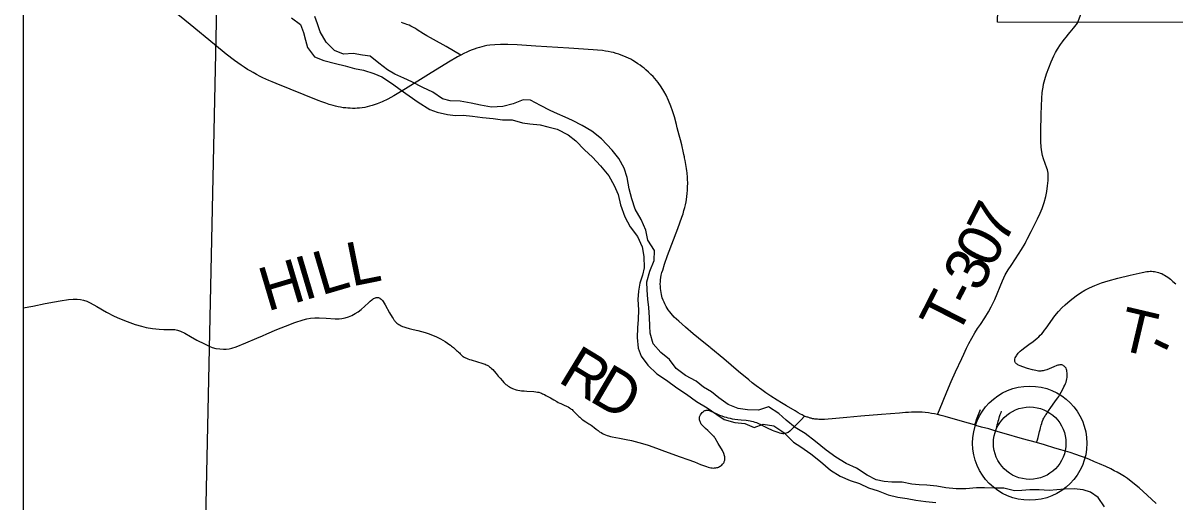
# Model space of a CAD drawing. Extents: x 0 to 34, y 0 to 22.
# Drawn here: x 2.1 to 3.6, y 17.772 to 18.396 of the extents above; entities that cross this region are included whole.
import ezdxf

# ---------------------------------------------------------------- set-up
doc = ezdxf.new("R2010")
doc.units = 0
for name, color, linetype in [('GM_X_Corporation', 7, 'Continuous'), ('GM_X_Major_River', 7, 'Continuous'), ('GM_X_State_Route', 7, 'Continuous'), ('GM_X_Township_Road', 7, 'Continuous'), ('GM_X_Township_Road_Text', 7, 'Continuous'), ('GM_X_Township_Text', 7, 'Continuous'), ('GM_X_Unincorporated', 7, 'Continuous'), ('GM_X_Unincorporated_Location', 7, 'Continuous'), ('SH_Data', 7, 'Continuous')]:
    doc.layers.add(name, color=color, linetype=linetype)

msp = doc.modelspace()

# ---------------------------------------------------------------- linework, layer by layer
at = {"layer": 'GM_X_Corporation'}
msp.add_lwpolyline([(4.6584, 17.4085), (4.4004, 17.4134), (4.4034, 17.9703), (4.4042, 18.3894), (4.0024, 18.3976), (3.4726, 18.3965), (3.3689, 18.3973), (3.3767, 18.6788), (3.3859, 18.705), (3.3893, 18.721), (3.3872, 18.7823), (3.3779, 18.9241), (3.3711, 18.9531), (3.3709, 19.4088), (3.3147, 19.4093), (2.7824, 19.4152), (2.1, 19.4241), (2.1, 14.1)], dxfattribs=at)
msp.add_lwpolyline([(2.1, 18.4215), (2.1, 17.4478), (2.3314, 17.4451), (2.3525, 18.417)], close=True, dxfattribs=at)
at = {"layer": 'GM_X_Major_River'}
for points in [[(3.4461, 17.7878), (3.4359, 17.7869), (3.423, 17.7875), (3.4109, 17.7877), (3.4006, 17.7868), (3.3908, 17.7863), (3.3771, 17.7899), (3.3669, 17.7898), (3.3521, 17.7904), (3.3414, 17.7902), (3.3274, 17.7889), (3.3149, 17.7891), (3.3016, 17.7901), (3.2899, 17.7922), (3.277, 17.7935), (3.2667, 17.7941), (3.2572, 17.7948), (3.2447, 17.7976), (3.2314, 17.7978), (3.2212, 17.7984), (3.2109, 17.8006), (3.199, 17.8069), (3.1853, 17.8158), (3.1719, 17.8217), (3.1585, 17.8302), (3.1459, 17.8395), (3.1317, 17.8507), (3.1183, 17.8611), (3.1053, 17.8689), (3.0938, 17.8786), (3.0842, 17.8872), (3.0708, 17.8958), (3.0576, 17.8914), (3.0432, 17.892), (3.0311, 17.8937), (3.0181, 17.8989), (3.0062, 17.9074), (2.9966, 17.9152), (2.9859, 17.9212), (2.9764, 17.9294), (2.9626, 17.9368), (2.9503, 17.9457), (2.9418, 17.9574), (2.9303, 17.9667), (2.9203, 17.9779), (2.9167, 17.9919), (2.9162, 18.0014), (2.9157, 18.012), (2.9148, 18.0253), (2.9135, 18.0362), (2.9126, 18.048), (2.9124, 18.0586), (2.916, 18.0727), (2.9219, 18.0864), (2.9221, 18.0997), (2.9136, 18.1129), (2.9111, 18.1261), (2.9049, 18.14), (2.8971, 18.1532), (2.8927, 18.1668), (2.8892, 18.1797), (2.8867, 18.1948), (2.8827, 18.2069), (2.8757, 18.2193), (2.8669, 18.2305), (2.8534, 18.2452), (2.8407, 18.2552), (2.8281, 18.2626), (2.8155, 18.2689), (2.806, 18.2733), (2.7957, 18.2778), (2.7862, 18.2822), (2.7739, 18.2885), (2.7606, 18.2955), (2.7511, 18.2961), (2.7383, 18.2906), (2.7247, 18.287), (2.7099, 18.2865), (2.6958, 18.2889), (2.6833, 18.2914), (2.6692, 18.2942), (2.6563, 18.2948), (2.6461, 18.297), (2.6334, 18.3059), (2.6205, 18.3118), (2.6063, 18.3192), (2.596, 18.324), (2.5842, 18.3295), (2.5746, 18.3351), (2.5632, 18.3436), (2.552, 18.3526), (2.5418, 18.3543), (2.53, 18.3561), (2.5171, 18.3555), (2.5057, 18.3603), (2.4945, 18.3711), (2.4871, 18.3847), (2.4836, 18.3949), (2.48, 18.4047)], [(2.4494, 18.4028), (2.4612, 18.3942), (2.4652, 18.3836), (2.4676, 18.3738), (2.4704, 18.364), (2.4796, 18.352), (2.4918, 18.3472), (2.5067, 18.3432), (2.5196, 18.3404), (2.5314, 18.3368), (2.5432, 18.3346), (2.5569, 18.3303), (2.5672, 18.3259), (2.581, 18.3166), (2.5909, 18.3095), (2.6028, 18.3013), (2.6146, 18.2927), (2.6296, 18.2835), (2.6391, 18.2798), (2.6528, 18.2766), (2.663, 18.2756), (2.6729, 18.2757), (2.6854, 18.2747), (2.6983, 18.273), (2.712, 18.2717), (2.7241, 18.27), (2.737, 18.2698), (2.7504, 18.2661), (2.7599, 18.2648), (2.7735, 18.2634), (2.7834, 18.2609), (2.7956, 18.2577), (2.8097, 18.2503), (2.8197, 18.2424), (2.8312, 18.2308), (2.8416, 18.2211), (2.852, 18.2099), (2.8628, 18.1967), (2.8698, 18.1843), (2.8749, 18.1723), (2.8781, 18.159), (2.8836, 18.1432), (2.8906, 18.1304), (2.9002, 18.1176), (2.9061, 18.1044), (2.9082, 18.0915), (2.9088, 18.0771), (2.9066, 18.0672), (2.9033, 18.057), (2.9016, 18.0467), (2.9006, 18.0357), (2.9012, 18.0224), (2.901, 18.0095), (2.9, 17.9989), (2.8998, 17.986), (2.9011, 17.9724), (2.905, 17.9618), (2.9135, 17.9502), (2.9254, 17.9389), (2.938, 17.9304), (2.9514, 17.9207), (2.9641, 17.9122), (2.9771, 17.9028), (2.9909, 17.8943), (3.0035, 17.8858), (3.013, 17.8794), (3.0267, 17.8755), (3.04, 17.8741), (3.0522, 17.869), (3.0639, 17.8733), (3.0776, 17.8712), (3.0906, 17.8623), (3.1033, 17.8496), (3.1129, 17.8436), (3.1259, 17.8343), (3.1385, 17.8246), (3.1516, 17.8131), (3.1638, 17.8056), (3.1768, 17.7997), (3.1893, 17.7957), (3.2008, 17.7902), (3.2134, 17.7862), (3.2263, 17.7811), (3.2389, 17.7782), (3.251, 17.7761), (3.2624, 17.774), (3.2757, 17.7726), (3.2886, 17.7713)], [(3.5082, 17.7655), (3.4997, 17.7776), (3.4898, 17.7846), (3.4802, 17.7875), (3.4685, 17.7889), (3.456, 17.7884), (3.4461, 17.7878)]]:
    msp.add_lwpolyline(points, dxfattribs=at)
at = {"layer": 'GM_X_State_Route'}
for points in [[(2.9949, 17.973), (2.9865, 17.9798), (2.9724, 17.991), (2.9624, 17.9994), (2.9537, 18.0073), (2.948, 18.0128), (2.9439, 18.0173), (2.9421, 18.0196), (2.9402, 18.0221), (2.9388, 18.0242), (2.9375, 18.0264), (2.9365, 18.0281), (2.9357, 18.0299), (2.9346, 18.0324), (2.9334, 18.035), (2.9324, 18.0377), (2.9318, 18.0401), (2.9312, 18.0423), (2.9308, 18.0447), (2.9305, 18.0474), (2.9302, 18.0499), (2.93, 18.0526), (2.9298, 18.0561), (2.9299, 18.0586), (2.9301, 18.0615), (2.9306, 18.0644), (2.9311, 18.0674), (2.9319, 18.0707), (2.9329, 18.074), (2.9352, 18.0817), (2.9391, 18.0928), (2.9527, 18.1282), (2.9554, 18.1355), (2.9579, 18.1429), (2.9594, 18.1475), (2.9606, 18.1518), (2.9616, 18.1557), (2.9625, 18.1591), (2.9633, 18.163), (2.9638, 18.1662), (2.9644, 18.17), (2.9649, 18.1738), (2.9652, 18.1781), (2.9654, 18.182), (2.9656, 18.1876), (2.9654, 18.192), (2.9653, 18.1945), (2.9648, 18.2007), (2.9645, 18.2032), (2.964, 18.2063), (2.9621, 18.2167), (2.9614, 18.2203), (2.9612, 18.2215), (2.9606, 18.2246), (2.96, 18.227), (2.9576, 18.2373), (2.9559, 18.2439), (2.9544, 18.2499), (2.9519, 18.2595), (2.9509, 18.2637), (2.9481, 18.2739), (2.9458, 18.2817), (2.9437, 18.2875), (2.9406, 18.2951), (2.9375, 18.3019), (2.9345, 18.3074), (2.9311, 18.3127), (2.927, 18.3183), (2.9249, 18.3209), (2.9226, 18.3235), (2.9203, 18.3261), (2.9174, 18.3289), (2.9142, 18.332), (2.9109, 18.3349), (2.9086, 18.337), (2.9061, 18.3389), (2.9036, 18.3409), (2.9005, 18.3429), (2.8976, 18.345), (2.8942, 18.347), (2.8912, 18.3488), (2.8882, 18.3503), (2.8852, 18.3517), (2.8825, 18.3529), (2.879, 18.3543), (2.8758, 18.3555), (2.8723, 18.3565), (2.8687, 18.3575), (2.8656, 18.3582), (2.862, 18.3589), (2.8586, 18.3595), (2.8546, 18.36), (2.8478, 18.3608), (2.8422, 18.3612), (2.8107, 18.3633), (2.7678, 18.366), (2.7436, 18.3674), (2.7311, 18.3679), (2.7218, 18.368), (2.7143, 18.3676), (2.7079, 18.3671), (2.7039, 18.3665), (2.7005, 18.3658), (2.6973, 18.3651), (2.6944, 18.3643), (2.691, 18.3633), (2.6876, 18.3621), (2.6847, 18.361), (2.6815, 18.3598), (2.6778, 18.3581), (2.6741, 18.3562), (2.6701, 18.3541), (2.6658, 18.3519), (2.654, 18.345), (2.628, 18.3291), (2.5979, 18.3104), (2.5826, 18.3009), (2.5751, 18.2967), (2.5678, 18.2933), (2.5609, 18.2906), (2.5545, 18.2885), (2.5513, 18.2875), (2.5481, 18.2866), (2.545, 18.2859), (2.5416, 18.2854), (2.5383, 18.2851), (2.5352, 18.2849), (2.5323, 18.2848), (2.5292, 18.2848), (2.5259, 18.2849), (2.5231, 18.285), (2.5202, 18.2853), (2.5168, 18.2856), (2.5133, 18.2862), (2.5103, 18.2868), (2.5069, 18.2876), (2.5037, 18.2884), (2.4984, 18.29), (2.4941, 18.2915), (2.4891, 18.2932), (2.4842, 18.2951), (2.4297, 18.3171), (2.4242, 18.3194), (2.4199, 18.3212), (2.4161, 18.3229), (2.4124, 18.3247), (2.4087, 18.3265), (2.4038, 18.3291), (2.3995, 18.3314), (2.3959, 18.3335), (2.3923, 18.3356), (2.3879, 18.3383), (2.384, 18.3409), (2.3754, 18.347), (2.3646, 18.3553), (2.3491, 18.3678), (2.3175, 18.3939), (2.2945, 18.4128)], [(3.5756, 17.7696), (3.5637, 17.7805), (3.5531, 17.79), (3.545, 17.7969), (3.5381, 17.8022), (3.5341, 17.8051), (3.5299, 17.8077), (3.5248, 17.8105), (3.5209, 17.8125), (3.5162, 17.8148), (3.5097, 17.8179), (3.5017, 17.8215), (3.4951, 17.8243), (3.4878, 17.8274), (3.482, 17.8296), (3.477, 17.8315), (3.4707, 17.8338), (3.4633, 17.8363), (3.4514, 17.8399), (3.4437, 17.8421), (3.4301, 17.8461), (3.4196, 17.8491), (3.4016, 17.8542), (3.3774, 17.8611), (3.3668, 17.8641), (3.3639, 17.8649), (3.3574, 17.8669), (3.3482, 17.8694), (3.3405, 17.8716), (3.3389, 17.8721), (3.3232, 17.8765), (3.3005, 17.8832), (3.2956, 17.8845), (3.2909, 17.8856), (3.2867, 17.8865), (3.2829, 17.8872), (3.2791, 17.8878), (3.2748, 17.8884), (3.2709, 17.8887), (3.2681, 17.8889), (3.2659, 17.889), (3.2613, 17.889), (3.2568, 17.8888), (3.2528, 17.8886), (3.2489, 17.8882), (3.2412, 17.8876), (3.2177, 17.8856), (3.1911, 17.8835), (3.1725, 17.8818), (3.1583, 17.8804), (3.1437, 17.8792), (3.1407, 17.8792), (3.1385, 17.8792), (3.1364, 17.8793), (3.1344, 17.8795), (3.1329, 17.8796), (3.1312, 17.8798), (3.1296, 17.88), (3.1289, 17.8801), (3.1281, 17.8803), (3.1272, 17.8805), (3.1262, 17.8808), (3.1251, 17.8811), (3.1241, 17.8814), (3.123, 17.8817), (3.1218, 17.8821), (3.1209, 17.8825), (3.1197, 17.8829), (3.1186, 17.8833), (3.1176, 17.8838), (3.1159, 17.8845), (3.1144, 17.8852), (3.1122, 17.8863), (3.1093, 17.8879), (3.1053, 17.8904), (3.094, 17.8971), (3.0876, 17.901), (3.0818, 17.9046), (3.0737, 17.9097), (3.0674, 17.9139), (3.0619, 17.9178), (3.0548, 17.9231), (3.0494, 17.9272), (3.0449, 17.9309), (3.0317, 17.9419), (3.0123, 17.9584), (2.9956, 17.9724), (2.9949, 17.973)]]:
    msp.add_lwpolyline(points, dxfattribs=at)
at = {"layer": 'GM_X_Township_Road'}
for points in [[(3.4728, 18.3959), (3.4792, 18.4119), (3.4825, 18.4233), (3.4842, 18.4343), (3.4842, 18.4433), (3.4814, 18.4637), (3.4776, 18.4839), (3.4749, 18.4943), (3.4723, 18.5017), (3.4682, 18.5112), (3.4632, 18.5211), (3.453, 18.5401), (3.4481, 18.5481), (3.4438, 18.5545), (3.4371, 18.5628), (3.4208, 18.5818), (3.4137, 18.5908), (3.4021, 18.6078), (3.3937, 18.6231), (3.3877, 18.6387), (3.3841, 18.649), (3.3782, 18.6646), (3.3769, 18.6783)], [(2.6701, 18.3541), (2.6607, 18.3597), (2.6508, 18.3655), (2.6343, 18.3746), (2.6304, 18.3767), (2.6256, 18.3795), (2.6213, 18.382), (2.6134, 18.387), (2.6109, 18.3887), (2.6076, 18.3905), (2.605, 18.3919), (2.6026, 18.393), (2.5998, 18.3942), (2.5974, 18.395), (2.5951, 18.3958), (2.5926, 18.3965)], [(3.2909, 17.8856), (3.2934, 17.8918), (3.3028, 17.9153), (3.3085, 17.9286), (3.3143, 17.9416), (3.3223, 17.9589), (3.3248, 17.9646), (3.3266, 17.9685), (3.3283, 17.9724), (3.3313, 17.9784), (3.3393, 17.9922), (3.3429, 17.9979), (3.3465, 18.0031), (3.3524, 18.0118), (3.3572, 18.0198), (3.3608, 18.0261), (3.3652, 18.0358), (3.3754, 18.0599), (3.379, 18.0678), (3.3827, 18.0743), (3.3865, 18.0799), (3.3924, 18.0887), (3.4001, 18.1007), (3.4047, 18.1088), (3.4061, 18.1115), (3.4074, 18.1143), (3.4125, 18.1242), (3.421, 18.1408), (3.4244, 18.1481), (3.427, 18.1544), (3.4295, 18.1621), (3.4316, 18.1699), (3.433, 18.1766), (3.4341, 18.184), (3.4347, 18.1908), (3.4348, 18.1944), (3.4348, 18.1977), (3.4346, 18.2002), (3.4343, 18.2024), (3.4338, 18.2047), (3.433, 18.2069), (3.4286, 18.2189), (3.4275, 18.2232), (3.4266, 18.2281), (3.4259, 18.2342), (3.4254, 18.2417), (3.4253, 18.2541), (3.4259, 18.2771), (3.4266, 18.2982), (3.427, 18.305), (3.4274, 18.3081), (3.4281, 18.3123), (3.4288, 18.3165), (3.4304, 18.3226), (3.4328, 18.3296), (3.4358, 18.3378), (3.4386, 18.3453), (3.4403, 18.3493), (3.442, 18.3532), (3.4443, 18.3574), (3.4468, 18.3618), (3.4508, 18.3681), (3.4534, 18.3717), (3.4556, 18.3746), (3.4585, 18.3781), (3.4609, 18.381), (3.4636, 18.3843), (3.4677, 18.3895), (3.4728, 18.3959)], [(3.4188, 17.9431), (3.4145, 17.944), (3.4079, 17.9458), (3.4017, 17.9478), (3.3983, 17.949), (3.3962, 17.95), (3.3952, 17.9506), (3.3943, 17.9512), (3.3935, 17.9518), (3.3928, 17.9526), (3.3923, 17.9533), (3.3919, 17.9542), (3.3916, 17.955), (3.3914, 17.9559), (3.3913, 17.9568), (3.3914, 17.9578), (3.3919, 17.9596), (3.3926, 17.9611), (3.3934, 17.9623), (3.394, 17.9633), (3.3947, 17.9644), (3.3956, 17.9655), (3.3968, 17.9667), (3.3984, 17.9683), (3.4004, 17.97), (3.4044, 17.973), (3.4096, 17.9769), (3.4152, 17.9811), (3.4179, 17.9831), (3.4205, 17.9853), (3.4226, 17.9871), (3.4245, 17.9891), (3.4264, 17.991), (3.4282, 17.9932), (3.4302, 17.9956), (3.4321, 17.9981), (3.4436, 18.0142), (3.4482, 18.02), (3.4524, 18.0246), (3.4569, 18.0289), (3.4634, 18.0345), (3.4712, 18.0405), (3.4768, 18.0444), (3.4826, 18.0479), (3.4853, 18.0493), (3.4886, 18.051), (3.4954, 18.0539), (3.5041, 18.0572), (3.513, 18.0599), (3.5255, 18.0634), (3.5417, 18.0673), (3.5573, 18.0709), (3.5634, 18.072), (3.5656, 18.0723), (3.5677, 18.0724), (3.5694, 18.0724), (3.5714, 18.0723), (3.5731, 18.0722), (3.575, 18.0718), (3.5766, 18.0715), (3.5786, 18.0709), (3.5806, 18.0702), (3.5826, 18.0694), (3.5847, 18.0684), (3.5864, 18.0674), (3.5883, 18.0662), (3.5906, 18.0647), (3.594, 18.0621), (3.5973, 18.0593), (3.6011, 18.0561)], [(2.1, 18.0246), (2.1128, 18.027), (2.1286, 18.0303), (2.1408, 18.0326), (2.1482, 18.0339), (2.1592, 18.0356), (2.1654, 18.0361), (2.1703, 18.0361), (2.1747, 18.0357), (2.1789, 18.0347), (2.183, 18.0333), (2.1875, 18.0313), (2.1962, 18.0264), (2.2086, 18.0193), (2.2185, 18.0141), (2.2258, 18.0107), (2.2356, 18.0068), (2.2461, 18.0031), (2.2544, 18.0007), (2.2605, 17.9992), (2.2684, 17.9978), (2.2771, 17.9968), (2.2833, 17.9966), (2.2891, 17.9967), (2.2937, 17.9967), (2.2975, 17.9966), (2.3013, 17.9958), (2.305, 17.9944), (2.3106, 17.9916), (2.3179, 17.9876), (2.3265, 17.9828), (2.3363, 17.9777), (2.3424, 17.9748), (2.3464, 17.9732), (2.3512, 17.972), (2.3561, 17.9712), (2.361, 17.9709), (2.3647, 17.971), (2.3684, 17.9715), (2.372, 17.9724), (2.3773, 17.9741), (2.39, 17.9792), (2.4043, 17.9853), (2.4117, 17.9885), (2.4174, 17.9909), (2.4305, 17.9964), (2.4419, 18.001), (2.4541, 18.0056), (2.4647, 18.0092), (2.4694, 18.0105), (2.4743, 18.0114), (2.4799, 18.0119), (2.4855, 18.0119), (2.4948, 18.0114), (2.5066, 18.0105), (2.5115, 18.0105), (2.5152, 18.0109), (2.5195, 18.0117), (2.5237, 18.0129), (2.5282, 18.0148), (2.5326, 18.0172), (2.5363, 18.0196), (2.5401, 18.0227), (2.5497, 18.0315), (2.552, 18.0335), (2.554, 18.0352), (2.5553, 18.0361), (2.5565, 18.0369), (2.5577, 18.0375), (2.5588, 18.0379), (2.5596, 18.0382), (2.5606, 18.0384), (2.5619, 18.0384), (2.5627, 18.0383), (2.5636, 18.038), (2.5644, 18.0376), (2.5652, 18.0371), (2.5661, 18.0363), (2.5671, 18.0354), (2.568, 18.0342), (2.5689, 18.0329), (2.5716, 18.0287), (2.5772, 18.0184), (2.5806, 18.0125), (2.5818, 18.0107), (2.5828, 18.0092), (2.5836, 18.0082), (2.5842, 18.0074), (2.5855, 18.0061), (2.5866, 18.005), (2.5878, 18.0041), (2.5893, 18.003), (2.5909, 18.0021), (2.5924, 18.0013), (2.5942, 18.0005), (2.596, 17.9999), (2.5983, 17.9991), (2.6028, 17.998), (2.6079, 17.9967), (2.6139, 17.9952), (2.6188, 17.9939), (2.6234, 17.9925), (2.6277, 17.9912), (2.6311, 17.99), (2.6341, 17.9889), (2.6374, 17.9874), (2.6403, 17.9861), (2.6436, 17.9845), (2.6466, 17.9827), (2.6495, 17.981), (2.6528, 17.9789), (2.6546, 17.9776), (2.6564, 17.9762), (2.658, 17.975), (2.6592, 17.9739), (2.6603, 17.9729), (2.6618, 17.9717), (2.6632, 17.9705), (2.6645, 17.9694), (2.6657, 17.9683), (2.6669, 17.9671), (2.6681, 17.9661), (2.6693, 17.9649), (2.6704, 17.9637), (2.6713, 17.9628), (2.6724, 17.9619), (2.6732, 17.9612), (2.6742, 17.9605), (2.6753, 17.9599), (2.6763, 17.9595), (2.6774, 17.959), (2.6791, 17.9584), (2.6815, 17.9576), (2.6837, 17.9569), (2.6862, 17.9561), (2.6891, 17.9553), (2.6916, 17.9545), (2.6976, 17.9527), (2.6998, 17.9519), (2.7016, 17.9512), (2.703, 17.9506), (2.7044, 17.9499), (2.706, 17.949), (2.7075, 17.9479), (2.7086, 17.9471), (2.7099, 17.9459), (2.7115, 17.9443), (2.7133, 17.9424), (2.7159, 17.9393), (2.7188, 17.9357), (2.7211, 17.933), (2.7241, 17.9296), (2.7259, 17.9276), (2.7275, 17.9261), (2.7288, 17.9249), (2.7303, 17.9238), (2.7318, 17.9227), (2.7334, 17.9218), (2.7349, 17.9209), (2.7373, 17.9198), (2.7388, 17.9192), (2.7407, 17.9185), (2.7421, 17.9181), (2.7442, 17.9176), (2.7467, 17.9171), (2.7491, 17.9168), (2.7523, 17.9165), (2.7558, 17.9163), (2.7651, 17.9157), (2.7677, 17.9154), (2.77, 17.915), (2.7715, 17.9147), (2.7736, 17.914), (2.7751, 17.9135), (2.7765, 17.9129), (2.779, 17.9118), (2.7809, 17.9107), (2.7832, 17.9094), (2.7867, 17.9074), (2.7911, 17.9048), (2.7949, 17.9026), (2.797, 17.9016), (2.7988, 17.9007), (2.8003, 17.9), (2.8021, 17.8992), (2.8048, 17.898), (2.8077, 17.8967), (2.8097, 17.8957), (2.8115, 17.8945), (2.8128, 17.8937), (2.8138, 17.8929), (2.8148, 17.8921), (2.8158, 17.891), (2.8207, 17.8863), (2.8217, 17.8853), (2.8229, 17.8842), (2.8238, 17.8833), (2.8248, 17.8824), (2.8259, 17.8815), (2.8268, 17.8807), (2.8278, 17.8797), (2.8288, 17.879), (2.8307, 17.8776), (2.8329, 17.8762), (2.8341, 17.8754), (2.8353, 17.8746), (2.8369, 17.8736), (2.8383, 17.8727), (2.8397, 17.8718), (2.8413, 17.8706), (2.8437, 17.8689), (2.8464, 17.8667), (2.8488, 17.8649), (2.8508, 17.8634), (2.8526, 17.8622), (2.8545, 17.8612), (2.8564, 17.8603), (2.8583, 17.8594), (2.8605, 17.8585), (2.8624, 17.8579), (2.8648, 17.8572), (2.8671, 17.8567), (2.8768, 17.855), (2.8852, 17.8534), (2.8924, 17.8517), (2.9067, 17.8478), (2.9138, 17.8457), (2.9249, 17.8419), (2.9353, 17.838), (2.9557, 17.8307), (2.9655, 17.8271), (2.9742, 17.8239), (2.9821, 17.8208), (2.9901, 17.8178), (2.9923, 17.8171), (2.994, 17.8165), (2.9956, 17.8163), (2.9972, 17.8161), (2.9989, 17.816), (3.0003, 17.8161), (3.0019, 17.8163), (3.0033, 17.8166), (3.0045, 17.8169), (3.0056, 17.8173), (3.0068, 17.8178), (3.0078, 17.8184), (3.0089, 17.8191), (3.0097, 17.8199), (3.0108, 17.8209), (3.0118, 17.822), (3.0123, 17.8227), (3.0128, 17.8236), (3.0131, 17.8244), (3.0134, 17.8253), (3.0136, 17.8262), (3.0138, 17.8271), (3.0139, 17.8283), (3.0138, 17.8295), (3.0137, 17.8307), (3.0135, 17.8319), (3.0125, 17.8348), (3.0106, 17.8387), (3.005, 17.8481), (3.001, 17.8549), (3.0003, 17.856), (2.9997, 17.8569), (2.999, 17.8577), (2.9981, 17.8586), (2.9975, 17.8593), (2.9965, 17.8602), (2.9949, 17.8618), (2.9916, 17.8648), (2.9886, 17.8675), (2.9846, 17.8714), (2.9838, 17.8723), (2.9831, 17.8733), (2.9825, 17.8743), (2.982, 17.8754), (2.9815, 17.8765), (2.9812, 17.8777), (2.981, 17.8789), (2.9809, 17.8801), (2.9808, 17.8809), (2.9809, 17.8819), (2.981, 17.8828), (2.9813, 17.8836), (2.9815, 17.8844), (2.9819, 17.8853), (2.9829, 17.8868), (2.9841, 17.8882), (2.9856, 17.8894), (2.987, 17.8904), (2.9878, 17.8908), (2.9887, 17.8912), (2.9896, 17.8913), (2.9905, 17.8914), (2.9923, 17.8913), (2.9947, 17.8906), (3.0032, 17.8867), (3.0068, 17.8851), (3.0101, 17.8839), (3.0128, 17.8829), (3.0154, 17.8821), (3.0179, 17.8814), (3.0208, 17.8808), (3.0233, 17.8802), (3.0269, 17.8797), (3.0309, 17.8792), (3.0349, 17.8788), (3.0417, 17.8783), (3.0443, 17.878), (3.0466, 17.8776), (3.0487, 17.8771), (3.0508, 17.8766), (3.0529, 17.8759), (3.0549, 17.8752), (3.0566, 17.8745), (3.0583, 17.8738), (3.0596, 17.8731), (3.0611, 17.8724), (3.063, 17.8714), (3.0688, 17.8685), (3.0756, 17.8654), (3.0776, 17.8646), (3.0803, 17.8636), (3.0829, 17.8626), (3.0849, 17.862), (3.0865, 17.8616), (3.088, 17.8613), (3.0893, 17.8612), (3.0905, 17.8612), (3.0914, 17.8613), (3.0923, 17.8614), (3.0933, 17.8616), (3.0942, 17.8619), (3.0953, 17.8624), (3.0963, 17.8629), (3.0983, 17.8643), (3.0992, 17.865), (3.1011, 17.8666), (3.1047, 17.87), (3.109, 17.8744), (3.1132, 17.879), (3.1176, 17.8838)], [(3.4196, 17.8491), (3.4208, 17.8528), (3.4216, 17.856), (3.4226, 17.8598), (3.4235, 17.8635), (3.4242, 17.8664), (3.4248, 17.8686), (3.4257, 17.8719), (3.4264, 17.8741), (3.4272, 17.8764), (3.4279, 17.8782), (3.4285, 17.8796), (3.4291, 17.8809), (3.4297, 17.8821), (3.4304, 17.8832), (3.4311, 17.8843), (3.432, 17.8859), (3.4329, 17.8871), (3.4339, 17.8887), (3.436, 17.8917), (3.4374, 17.8937), (3.4415, 17.8991), (3.4458, 17.9052), (3.4473, 17.9073), (3.4486, 17.9094), (3.4502, 17.912), (3.4519, 17.915), (3.4539, 17.9188), (3.4554, 17.9219), (3.4564, 17.9239), (3.4574, 17.9262), (3.4581, 17.9281), (3.4586, 17.9301), (3.4591, 17.9321), (3.4594, 17.9342), (3.4596, 17.9359), (3.4597, 17.9378), (3.4597, 17.9389), (3.4596, 17.9402), (3.4593, 17.9417), (3.459, 17.9431), (3.4586, 17.9446), (3.4581, 17.946), (3.4574, 17.947), (3.4566, 17.948), (3.4557, 17.9487), (3.4546, 17.9494), (3.4537, 17.95), (3.4526, 17.9503), (3.4515, 17.9504), (3.4501, 17.9504), (3.4488, 17.9502), (3.4476, 17.9499), (3.4463, 17.9495), (3.4423, 17.948), (3.4332, 17.9441), (3.4314, 17.9435), (3.4297, 17.943), (3.4282, 17.9427), (3.4267, 17.9425), (3.4252, 17.9424), (3.4236, 17.9424), (3.4223, 17.9424), (3.4205, 17.9427), (3.4188, 17.9431)], [(3.3389, 17.8721), (3.3405, 17.8759), (3.3417, 17.8791), (3.3465, 17.8923)], [(3.3668, 17.8641), (3.3672, 17.8662), (3.3676, 17.8681), (3.368, 17.8699), (3.3686, 17.8724), (3.3691, 17.8746), (3.3698, 17.8771), (3.3704, 17.8794), (3.3716, 17.8831), (3.372, 17.8843), (3.3725, 17.8857), (3.3735, 17.8884), (3.3742, 17.8902)]]:
    msp.add_lwpolyline(points, dxfattribs=at)
at = {"layer": 'GM_X_Township_Text'}
msp.add_lwpolyline([(2.1, 19.4241), (2.1, 16.074), (2.3294, 16.0685), (2.5414, 16.0663), (3.0911, 16.0497), (3.9428, 16.0275), (4.0565, 16.0246), (4.383, 16.0223), (4.3994, 17.3911), (4.4004, 17.4134)], dxfattribs=at)
at = {"layer": 'GM_X_Unincorporated'}
for radius in [0.0744, 0.0472]:
    msp.add_circle((3.4108, 17.8484), radius, dxfattribs=at)
at = {"layer": 'GM_X_Unincorporated_Location'}
msp.add_line((3.4108, 17.8484), (3.4108, 17.8484), dxfattribs=at)
at = {"layer": 'SH_Data'}
msp.add_line((2.1, 20.9), (2.1, 14.1), dxfattribs=at)

# ---------------------------------------------------------------- texts
at = {"layer": 'GM_X_Township_Road_Text'}
for s, rotation, p in [('7', 63.0248, (3.3775, 18.1056)), ('0', 62.9781, (3.3617, 18.0746)), ('L', 11.3889, (2.5278, 18.0525)), ('I', 16.5347, (2.466, 18.0342)), ('L', 16.4099, (2.4883, 18.0408)), ('3', 62.9755, (3.3459, 18.0437)), ('H', 16.5293, (2.418, 18.0199)), ('T', 62.9755, (3.3161, 17.9853)), ('-', 62.9755, (3.3354, 18.0231)), ('T', 346.7381, (3.5233, 17.9713)), ('R', 328.6661, (2.795, 17.9293)), ('-', 334.3427, (3.5616, 17.9627)), ('D', 329.5159, (2.8356, 17.9046))]:
    msp.add_text(s, height=0.0568, rotation=rotation, dxfattribs=at).set_placement(p)

doc.saveas('drawing.dxf')
